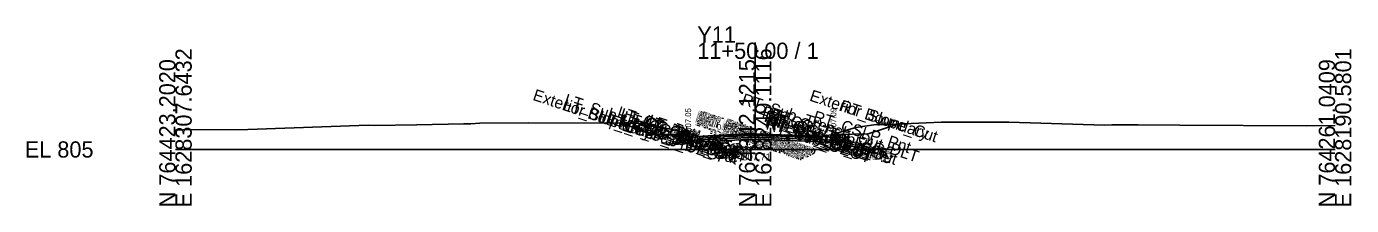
# Model space of a CAD drawing. Extents: x -26 to 203, y -10 to 6017.
# Drawn here: x -25.7 to 202.8, y 2990.3 to 3021.3 of the extents above; entities that cross this region are included whole.
import ezdxf

# ---------------------------------------------------------------- set-up
doc = ezdxf.new("R2010")
doc.units = 0
for name, color, linetype in [('Default', 7, 'Continuous'), ('Exist Cross Section Cell', 7, 'Continuous'), ('Exist XS Center Line Elevation Label', 7, 'Continuous'), ('Exist XS Ground Line', 7, 'Continuous'), ('Prop CMT Conc Surface', 7, 'Continuous'), ('Prop CMT Concrete Structures', 7, 'Continuous'), ('Prop CMT Pvmt Course 1', 7, 'Continuous'), ('Prop CMT Pvmt Course 1 CG', 7, 'Continuous'), ('Prop CMT Pvmt Course 2', 7, 'Continuous'), ('Prop CMT Pvmt Course 3', 7, 'Continuous'), ('Prop CMT Pvmt Surface', 7, 'Continuous'), ('Prop CMT Pvmt Wedge Surface 1', 7, 'Continuous'), ('Prop CMT Pvmt Wedge Surface 2', 7, 'Continuous'), ('Prop CMT Pvmt Wedge Surface 3', 7, 'Continuous'), ('Prop CMT Slope Grass', 7, 'Continuous'), ('Prop CMT Subgrade Earthwork', 7, 'Continuous'), ('Prop XS Hydro Elevations', 7, 'Continuous'), ('Prop XS SE Text', 7, 'Continuous'), ('Prop XS Side Slope Text', 7, 'Continuous'), ('Scratch_Level_0', 7, 'Continuous')]:
    doc.layers.add(name, color=color, linetype=linetype)

msp = doc.modelspace()

# ---------------------------------------------------------------- linework, layer by layer
at = {"layer": 'Exist Cross Section Cell'}
for p, q in [((100, 3000), (100, 3018.46)), ((0, 3000), (100, 3000)), ((100, 3000), (200, 3000))]:
    msp.add_line(p, q, dxfattribs=at)
at = {"layer": 'Exist XS Ground Line'}
msp.add_lwpolyline([(0, 3003.34), (1.26, 3003.39), (12.49, 3003.44), (33.24, 3004.19), (34.29, 3004.16), (41.55, 3004.25), (49.72, 3004.44), (50.33, 3004.44), (50.95, 3004.45), (52.52, 3004.54), (60.85, 3004.61), (77.8, 3004.52), (81.36, 3004.47), (81.79, 3004.29), (84.06, 3003.8), (86.14, 3003.35), (88.41, 3002.75), (88.75, 3002.58), (90.44, 3002.26), (91.86, 3002.34), (99.38, 3002.74), (100, 3002.71), (106.01, 3002.49), (111.49, 3002.31), (112.4, 3002.44), (113.33, 3002.57), (116.57, 3003.56), (117.36, 3003.78), (120.84, 3004.3), (123.03, 3004.34), (132.04, 3004.7), (135.49, 3004.71), (137.37, 3004.74), (141.71, 3004.7), (143.41, 3004.7), (143.71, 3004.69), (160.21, 3004.2), (161.51, 3004.25), (166.04, 3004.23), (173.25, 3004.22), (195.15, 3004.06), (200, 3004.17)], dxfattribs=at)
at = {"layer": 'Prop CMT Conc Surface'}
for points in [[(88.44, 3002.05), (88.43, 3002.55), (87.93, 3002.55)], [(90.44, 3002.23), (88.44, 3002.05)], [(111.49, 3002.25), (113.49, 3002.09)], [(113.49, 3002.09), (113.49, 3002.59), (113.99, 3002.59)]]:
    msp.add_lwpolyline(points, dxfattribs=at)
at = {"layer": 'Prop CMT Concrete Structures'}
for points in [[(90.44, 3002.23), (88.44, 3002.05), (88.43, 3002.55), (87.93, 3002.55)], [(87.93, 3002.55), (87.94, 3001.52), (90.44, 3001.65)], [(90.44, 3001.65), (90.44, 3002.23)], [(111.49, 3002.25), (113.49, 3002.09), (113.49, 3002.59), (113.99, 3002.59)], [(113.99, 3002.59), (113.99, 3001.57), (111.49, 3001.67)], [(111.49, 3001.67), (111.49, 3002.25)]]:
    msp.add_lwpolyline(points, dxfattribs=at)
at = {"layer": 'Prop CMT Pvmt Course 1'}
for points in [[(100, 3002.71), (90.44, 3002.23)], [(90.44, 3001.98), (100, 3002.46)], [(90.44, 3002.23), (90.44, 3001.98)], [(100, 3002.46), (100, 3002.71)], [(100, 3002.71), (111.49, 3002.25)], [(100, 3002.46), (100, 3002.71)], [(111.49, 3002), (100, 3002.46)], [(111.49, 3002.25), (111.49, 3002)]]:
    msp.add_lwpolyline(points, dxfattribs=at)
msp.add_lwpolyline([(100, 3002.46), (100, 3002.58), (100, 3002.58), (100, 3002.46)], close=True, dxfattribs=at)
msp.add_lwpolyline([(100, 3002.46), (100, 3002.58), (100, 3002.58), (100, 3002.46)], close=True, dxfattribs=at)
at = {"layer": 'Prop CMT Pvmt Course 1 CG'}
for points in [[(90.44, 3001.65), (87.44, 3001.5), (87.08, 3001.15)], [(87.08, 3001.15), (90.44, 3001.32)], [(90.44, 3001.32), (90.44, 3001.65)], [(111.49, 3001.67), (114.49, 3001.55), (114.84, 3001.2)], [(111.49, 3001.33), (111.49, 3001.67)], [(114.84, 3001.2), (111.49, 3001.33)]]:
    msp.add_lwpolyline(points, dxfattribs=at)
at = {"layer": 'Prop CMT Pvmt Course 2'}
for points in [[(100, 3002.46), (90.44, 3001.98)], [(90.44, 3001.65), (100, 3002.13)], [(90.44, 3001.98), (90.44, 3001.65)], [(100, 3002.13), (100, 3002.46)], [(100, 3002.13), (100, 3002.46)], [(100, 3002.46), (111.49, 3002)], [(100, 3002.46), (100, 3002.46)], [(100, 3002.46), (100, 3002.46)], [(111.49, 3001.67), (100, 3002.13)], [(111.49, 3002), (111.49, 3001.67)]]:
    msp.add_lwpolyline(points, dxfattribs=at)
msp.add_lwpolyline([(100, 3002.46), (100, 3002.13), (100, 3002.13)], close=True, dxfattribs=at)
msp.add_lwpolyline([(100, 3002.46), (100, 3002.13), (100, 3002.13)], close=True, dxfattribs=at)
at = {"layer": 'Prop CMT Pvmt Course 3'}
for points in [[(100, 3002.13), (90.44, 3001.65)], [(90.44, 3001.32), (100, 3001.79)], [(90.44, 3001.65), (90.44, 3001.32)], [(100, 3001.79), (100, 3002.13)], [(100, 3002.13), (111.49, 3001.67)], [(100, 3001.79), (100, 3002.13)], [(100, 3002.13), (100, 3002.13), (100, 3001.79), (100, 3001.79)], [(100, 3001.79), (100, 3002.13)], [(100, 3002.13), (100, 3002.13), (100, 3001.79), (100, 3001.79)], [(100, 3001.79), (100, 3002.13)], [(111.49, 3001.33), (100, 3001.79)], [(111.49, 3001.67), (111.49, 3001.33)]]:
    msp.add_lwpolyline(points, dxfattribs=at)
at = {"layer": 'Prop CMT Pvmt Surface'}
for points in [[(100, 3002.71), (90.44, 3002.23)], [(100, 3002.71), (111.49, 3002.25)]]:
    msp.add_lwpolyline(points, dxfattribs=at)
at = {"layer": 'Prop CMT Pvmt Wedge Surface 1'}
for points in [[(100, 3002.71), (100, 3002.46), (100, 3002.46)], [(100, 3002.71), (100, 3002.46), (100, 3002.46)], [(100, 3002.46), (100, 3002.58)], [(100, 3002.46), (100, 3002.58)]]:
    msp.add_lwpolyline(points, dxfattribs=at)
at = {"layer": 'Prop CMT Pvmt Wedge Surface 2'}
for points in [[(100, 3002.71), (100, 3002.46)], [(100, 3002.71), (100, 3002.46)], [(100, 3002.46), (100, 3002.46)], [(100, 3002.46), (100, 3002.46)]]:
    msp.add_lwpolyline(points, dxfattribs=at)
at = {"layer": 'Prop CMT Pvmt Wedge Surface 3'}
for points in [[(100, 3002.71), (100, 3002.13)], [(100, 3002.71), (100, 3002.13)], [(100, 3002.13), (100, 3002.13)], [(100, 3002.13), (100, 3002.13)]]:
    msp.add_lwpolyline(points, dxfattribs=at)
at = {"layer": 'Prop CMT Slope Grass'}
for points in [[(87.93, 3002.55), (82.43, 3002.66), (76.84, 3004.53)], [(113.99, 3002.59), (119.49, 3002.7), (124.6, 3004.4)]]:
    msp.add_lwpolyline(points, dxfattribs=at)
at = {"layer": 'Prop CMT Subgrade Earthwork'}
for points in [[(90.44, 3001.32), (87.08, 3001.15), (85.63, 3002.6)], [(100, 3001.79), (90.44, 3001.32)], [(100, 3001.79), (111.49, 3001.33)], [(111.49, 3001.33), (114.84, 3001.2), (116.27, 3002.64)]]:
    msp.add_lwpolyline(points, dxfattribs=at)

# ---------------------------------------------------------------- texts
at = {"layer": 'Default'}
msp.add_text('-', height=0.0001, dxfattribs=at).set_placement((0, 3000))
at = {"layer": 'Exist Cross Section Cell'}
for s, p in [('Y11', (90, 3018.46)), ('11+50.00 / 1', (90, 3015.66)), ('EL 805', (-26, 2998.6))]:
    msp.add_text(s, height=2.8, dxfattribs=at).set_placement(p)
for s, p in [('E 1628307.6432', (2.8, 2990)), ('E 1628249.1116', (102.8, 2990)), ('E 1628190.5801', (202.8, 2990)), ('N 764423.2020', (0, 2990)), ('N 764342.1215', (100, 2990)), ('N 764261.0409', (200, 2990))]:
    msp.add_text(s, height=2.8, rotation=90, dxfattribs=at).set_placement(p)
at = {"layer": 'Exist XS Center Line Elevation Label'}
msp.add_text('807.71', height=1.2, dxfattribs=at).set_placement((97.77, 2998.11))
at = {"layer": 'Prop XS Hydro Elevations'}
for s, p in [('807.05', (88.94, 3003.05)), ('807.09', (113.99, 3003.09))]:
    msp.add_text(s, height=1, rotation=90, dxfattribs=at).set_placement(p)
at = {"layer": 'Prop XS SE Text'}
for s, rotation, p in [('0.050', 2.8624, (93.42, 3003.38)), ('0.040', 357.7094, (104.04, 3003.55))]:
    msp.add_text(s, height=1, rotation=rotation, dxfattribs=at).set_placement(p)
at = {"layer": 'Prop XS Side Slope Text'}
for rotation, p in [(341.5668, (79.13, 3004.55)), (18.4332, (121.06, 3004.01))]:
    msp.add_text('3:1', height=1, rotation=rotation, dxfattribs=at).set_placement(p)
at = {"layer": 'Scratch_Level_0'}
for s, p in [('Exterior Boundary', (61.49, 3008.59)), ('Exterior Boundary', (109.24, 3008.47)), ('LT_Slope_Cut', (66.7, 3006.85)), ('LT_Sub_Trench_Out_DLT', (66.88, 3007.79)), ('RT_Sub_Trench_Out_DLT', (97.48, 3007.85)), ('RT_CG_Top_Face', (101.04, 3005.69)), ('RT_Slope_Cut', (114.41, 3006.75)), ('LT_CSLP_Pnt', (72.8, 3004.82)), ('LT_CG1_Shelf_Out', (74.36, 3004.8)), ('LT_CG_Top_Face', (76.03, 3005.63)), ('LT_CG_Top_BOC', (76.5, 3005.31)), ('LT_CG_Bot_BOC', (76.53, 3004.27)), ('LT_CG_Top_Gut', (76.96, 3004.82)), ('LT_CG_Bot_IE', (80.55, 3003.89)), ('LT_Sub_OEOT', (80.71, 3003.5)), ('LT_PV2_OEOT', (80.8, 3004.14)), ('LT_PV3_OEOT', (80.8, 3003.81)), ('LT_PV1_OEOT', (81.33, 3004.21)), ('RT_Sub_OEEOP', (89.41, 3004.27)), ('LT_Sub_OEEOP', (89.45, 3004.26)), ('RT_PV2_OEEOP', (89.49, 3004.91)), ('RT_PV3_OEEOP', (89.49, 3004.57)), ('LT_PV2_OEEOP', (89.54, 3004.89)), ('LT_PV3_OEEOP', (89.54, 3004.56)), ('RT_Sub_IEEOP', (90.02, 3004.07)), ('RT_PV1_OEEOP', (90.03, 3004.85)), ('LT_Sub_IEEOP', (90.06, 3004.05)), ('LT_PV1_OEEOP', (90.08, 3004.84)), ('RT_PV2_IEEOP', (90.11, 3004.7)), ('RT_PV3_IEEOP', (90.11, 3004.37)), ('LT_PV2_IEEOP', (90.15, 3004.69)), ('LT_PV3_IEEOP', (90.15, 3004.36)), ('RT_PV1_IEEOP', (90.65, 3004.65)), ('LT_PV1_IEEOP', (90.69, 3004.63)), ('PV2_PGL', (93.9, 3003.44)), ('PV1_PGL', (94.44, 3003.51)), ('RT_CG1_Shelf_Out', (101.37, 3004.87)), ('RT_CG_Bot_IE', (101.56, 3003.92)), ('RT_Sub_OEOT', (101.72, 3003.54)), ('RT_PV2_OEOT', (101.81, 3004.17)), ('RT_PV3_OEOT', (101.81, 3003.84)), ('RT_CG_Top_Gut', (101.97, 3004.88)), ('RT_PV1_OEOT', (102.35, 3004.24)), ('RT_CG_Top_BOC', (102.52, 3005.36)), ('RT_CG_Bot_BOC', (102.54, 3004.33)), ('RT_Sub_OEOP', (105.1, 3003.39)), ('RT_CSLP_Pnt', (109.81, 3004.87)), ('LT_Sub_OEOP', (77.39, 3003.33)), ('Sub_PGL', (93.81, 3002.8)), ('PV3_PGL', (93.9, 3003.11))]:
    msp.add_text(s, height=2, rotation=341.5651, dxfattribs=at).set_placement(p)

doc.saveas('drawing.dxf')
